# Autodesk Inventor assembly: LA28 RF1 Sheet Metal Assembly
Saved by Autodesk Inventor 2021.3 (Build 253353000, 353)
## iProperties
Created: 2023-01
Part Number: LA28 RF1 Sheet Metal Assembly
Document SubType Name: Assembly
Designer: AdminForWorker
Title: LA28 RF1 Sheet Metal Assembly v3
Author: AdminForWorker
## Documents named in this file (8)
- c:\worker\convert-fusion-r08-cosv3\tmp\job-1\2\output\files\38fcaebe-cb34-4e03-bd92-f432653286df\LA28 RF1 Sheet Metal Assembly v3.iam
- c:\worker\convert-fusion-r08-cosv3\tmp\job-1\2\output\files\38fcaebe-cb34-4e03-bd92-f432653286df\LA28RF1 Front Rear C Channel^la28RF1 SHEET METAL ASSEMBLY.ipt
- c:\worker\convert-fusion-r08-cosv3\tmp\job-1\2\output\files\38fcaebe-cb34-4e03-bd92-f432653286df\LA28RF1 Center Bar^la28RF1 SHEET METAL ASSEMBLY.ipt
- c:\worker\convert-fusion-r08-cosv3\tmp\job-1\2\output\files\38fcaebe-cb34-4e03-bd92-f432653286df\AL28RF1 Outer Bar^la28RF1 SHEET METAL ASSEMBLY.ipt
- c:\worker\convert-fusion-r08-cosv3\tmp\job-1\2\output\files\38fcaebe-cb34-4e03-bd92-f432653286df\Inclinometer Mount Plate^la28RF1 SHEET METAL ASSEMBLY.ipt
- c:\worker\convert-fusion-r08-cosv3\tmp\job-1\2\output\files\38fcaebe-cb34-4e03-bd92-f432653286df\Stabilizing Tube^la28RF1 SHEET METAL ASSEMBLY.ipt
- c:\worker\convert-fusion-r08-cosv3\tmp\job-1\2\output\files\38fcaebe-cb34-4e03-bd92-f432653286df\Rear Connection Arm^la28RF1 SHEET METAL ASSEMBLY.ipt
- c:\worker\convert-fusion-r08-cosv3\tmp\job-1\2\output\files\38fcaebe-cb34-4e03-bd92-f432653286df\LA18 LA28 Front Connection Tongue^la28RF1 SHEET METAL ASSEMBLY.ipt
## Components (15 placed, 7 different names)
1. LA28RF1 Front Rear C Channel^la28RF1 SHEET METAL ASSEMBLY:1
2. LA28RF1 Front Rear C Channel^la28RF1 SHEET METAL ASSEMBLY:2
3. LA28RF1 Center Bar^la28RF1 SHEET METAL ASSEMBLY:1
4. LA28RF1 Center Bar^la28RF1 SHEET METAL ASSEMBLY:2
5. AL28RF1 Outer Bar^la28RF1 SHEET METAL ASSEMBLY:1
6. AL28RF1 Outer Bar^la28RF1 SHEET METAL ASSEMBLY:2
7. AL28RF1 Outer Bar^la28RF1 SHEET METAL ASSEMBLY:3
8. AL28RF1 Outer Bar^la28RF1 SHEET METAL ASSEMBLY:4
9. Inclinometer Mount Plate^la28RF1 SHEET METAL ASSEMBLY:1
10. Stabilizing Tube^la28RF1 SHEET METAL ASSEMBLY:1
11. Stabilizing Tube^la28RF1 SHEET METAL ASSEMBLY:2
12. Rear Connection Arm^la28RF1 SHEET METAL ASSEMBLY:1
13. Rear Connection Arm^la28RF1 SHEET METAL ASSEMBLY:2
14. LA18 LA28 Front Connection Tongue^la28RF1 SHEET METAL ASSEMBLY:1
15. LA18 LA28 Front Connection Tongue^la28RF1 SHEET METAL ASSEMBLY:2
